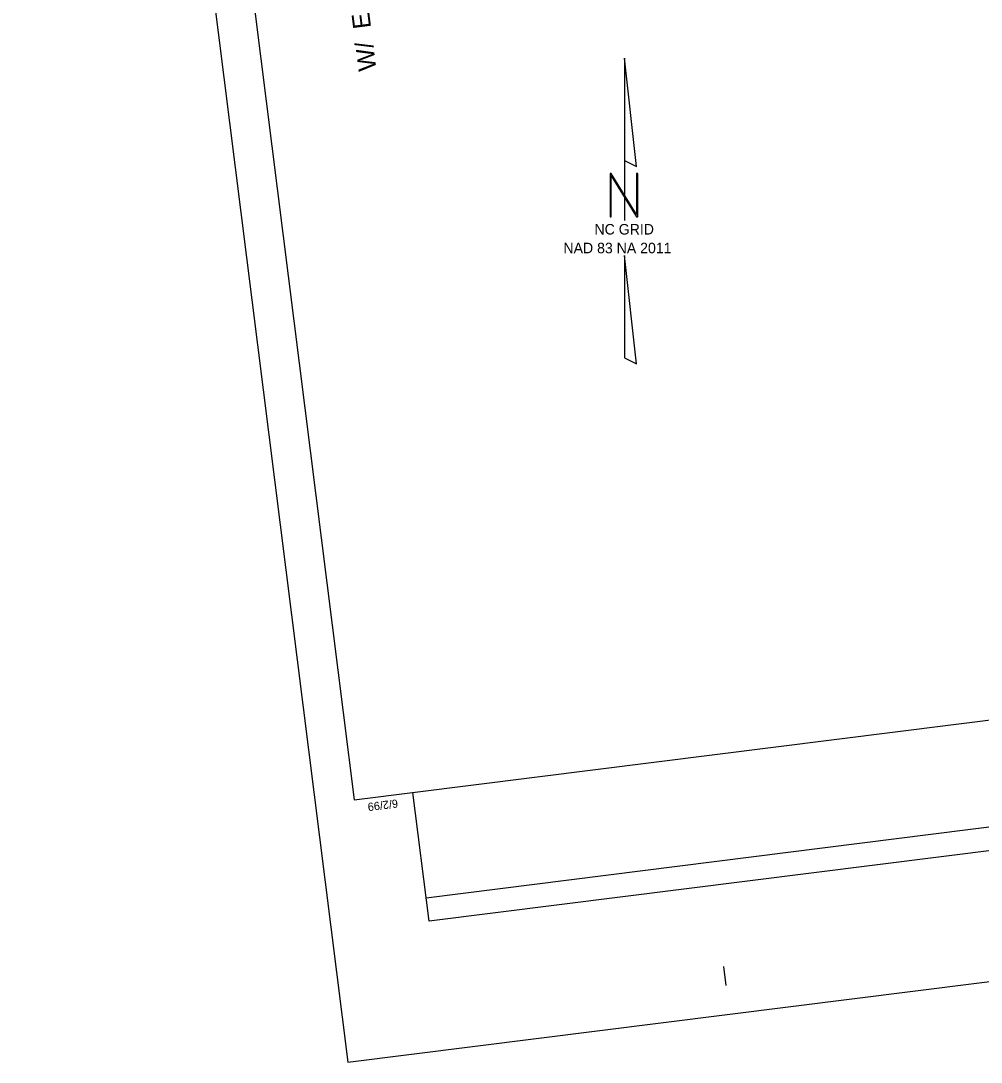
# Model space of a CAD drawing. Extents: x 477009 to 479892, y 492858 to 496862.
# Drawn here: x 477009 to 478377, y 492858 to 494341 of the extents above; entities that cross this region are included whole.
import ezdxf

# ---------------------------------------------------------------- set-up
doc = ezdxf.new("R2010")
doc.units = 0
for name, color, linetype in [('CTL North Arrow NAD 83 NA 2011 CELL', 7, 'Continuous'), ('CTL Sheet Border CELL', 7, 'Continuous'), ('Sheet Block Revision CELL', 7, 'Continuous'), ('Sheet Plot Border Outside CELL', 7, 'Continuous')]:
    doc.layers.add(name, color=color, linetype=linetype)

msp = doc.modelspace()

# ---------------------------------------------------------------- linework, layer by layer
at = {"layer": 'CTL North Arrow NAD 83 NA 2011 CELL'}
msp.add_line((477869.2, 494070.1), (477869.2, 494070.1), dxfattribs=at)
for points in [[(477868.8, 494288.3), (477868.8, 494142.5), (477886, 494133.9)], [(477848.2, 494062), (477850, 494062), (477850, 494120.3), (477886, 494062), (477887.7, 494062), (477887.7, 494123.7), (477886, 494123.7), (477886, 494065.4), (477850, 494123.7), (477848.2, 494123.7)], [(477868.8, 493861.3), (477886, 493852.7), (477868.8, 494007.1)]]:
    msp.add_lwpolyline(points, close=True, dxfattribs=at)
msp.add_lwpolyline([(477868.8, 494142.5), (477868.8, 494056.8)], dxfattribs=at)
at = {"layer": 'CTL Sheet Border CELL'}
msp.add_line((478013.7, 492966.6), (478010.2, 492994), dxfattribs=at)
msp.add_lwpolyline([(477068.9, 496527.4), (477483.7, 493231.4), (479790.9, 493521.7), (479376.1, 496817.7)], close=True, dxfattribs=at)
at = {"layer": 'Sheet Block Revision CELL'}
for p, q in [((479323.2, 493309.9), (477586.3, 493091.3)), ((479327.3, 493277), (477590.5, 493058.4)), ((477590.5, 493058.4), (477567.3, 493241.9))]:
    msp.add_line(p, q, dxfattribs=at)
at = {"layer": 'Sheet Plot Border Outside CELL'}
msp.add_lwpolyline([(479892, 493161.7), (479426.4, 496862), (477009.3, 496557.8), (477475, 492857.5)], close=True, dxfattribs=at)

# ---------------------------------------------------------------- texts
at = {"layer": 'CTL North Arrow NAD 83 NA 2011 CELL'}
for s, p in [('NC GRID', (477826.1, 494036.8)), ('NAD 83 NA 2011', (477781.9, 494010.1))]:
    msp.add_text(s, height=15, rotation=360, dxfattribs=at).set_placement(p)
at = {"layer": 'CTL Sheet Border CELL'}
for s, height, rotation, p in [('W/  EXISTING CENTERLINE ALIGNMENTS PRIOR TO CONSTRUCTION', 25.469, 97.1725, (477515.7, 494271.5)), ('6/2/99', 11.63, 187.1725, (477545.5, 493232.1))]:
    msp.add_text(s, height=height, rotation=rotation, dxfattribs=at).set_placement(p)

doc.saveas('drawing.dxf')
